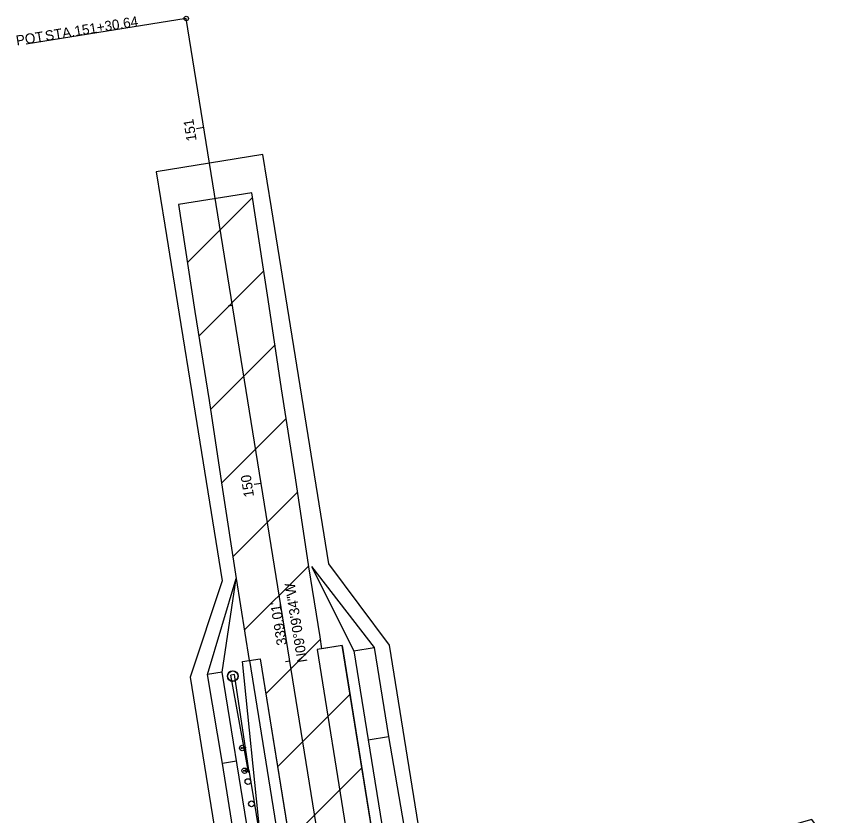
# Model space of a CAD drawing. Extents: x 195197 to 195502, y 336876 to 337459.
# Drawn here: x 195235.7 to 195462.3, y 337237.7 to 337459.5 of the extents above; entities that cross this region are included whole.
import ezdxf

# ---------------------------------------------------------------- set-up
doc = ezdxf.new("R2010")
doc.units = 0
for name, color, linetype in [('_CIVIL_CONSTRUCTION', 7, 'Continuous'), ('DR_P_Cells', 7, 'Continuous'), ('DR_P_Culvert', 7, 'Continuous'), ('DR_P_Headwall', 7, 'Continuous'), ('DT_X_Island', 7, 'Continuous'), ('DT_X_Terrain_Ground_Line', 7, 'Continuous'), ('DT_X_Void', 7, 'Continuous'), ('GK_Drainage_Nodes', 7, 'Continuous'), ('MD_P_Surface_Finished_Grade', 7, 'Continuous'), ('PV_P_Shoulder', 7, 'Continuous'), ('SC_Scratch1', 7, 'Continuous')]:
    doc.layers.add(name, color=color, linetype=linetype)

msp = doc.modelspace()

# ---------------------------------------------------------------- linework, layer by layer
at = {"layer": '_CIVIL_CONSTRUCTION'}
for points in [[(195306.55, 337406.32), (195304.16, 337421.13), (195274.54, 337416.35)], [(195274.54, 337416.35), (195276.93, 337401.54), (195280.91, 337376.86), (195284.89, 337352.18), (195288.87, 337327.5), (195292.85, 337302.82), (195283.99, 337276.07), (195287.97, 337251.38), (195291.95, 337226.7)], [(195415.16, 337192.63), (195427.5, 337191.06), (195439.23, 337196.72), (195449.47, 337204.35), (195456.27, 337211.36), (195462.31, 337228.75), (195456.54, 337236.65), (195437.52, 337231.22), (195415.54, 337222.22), (195377.07, 337205.9), (195368.38, 337218.99), (195350.22, 337217.12), (195339.28, 337284.98), (195322.46, 337307.59), (195306.55, 337406.32)]]:
    msp.add_lwpolyline(points, dxfattribs=at)
at = {"layer": 'DR_P_Cells'}
for p, q in [((195300.46, 337280.75), (195325.98, 337122.42)), ((195303.42, 337281.22), (195318.86, 337185.46))]:
    msp.add_line(p, q, dxfattribs=at)
at = {"layer": 'DR_P_Headwall'}
for p, q in [((195282.88, 337458.86), (195238.45, 337451.7)), ((195287.76, 337428.61), (195285.78, 337428.29)), ((195295.72, 337379.25), (195294.53, 337379.06)), ((195303.68, 337329.88), (195301.7, 337329.57)), ((195311.64, 337280.52), (195310.45, 337280.33))]:
    msp.add_line(p, q, dxfattribs=at)
msp.add_circle((195282.88, 337458.86), 0.6, dxfattribs=at)
at = {"layer": 'DT_X_Island'}
for p, q in [((195326.13, 337284.88), (195319.21, 337283.77)), ((195319.21, 337283.77), (195334.66, 337188.01)), ((195326.13, 337284.88), (195341.57, 337189.12))]:
    msp.add_line(p, q, dxfattribs=at)
at = {"layer": 'DT_X_Terrain_Ground_Line'}
msp.add_line((195300.3, 337250.33), (195300.38, 337249.84), dxfattribs=at)
at = {"layer": 'DT_X_Void'}
for p, q in [((195283.21, 337391.16), (195301.28, 337409.23)), ((195286.38, 337370.76), (195304.43, 337388.81)), ((195289.59, 337350.4), (195307.53, 337368.34)), ((195292.71, 337329.94), (195310.64, 337347.88)), ((195295.84, 337309.5), (195313.78, 337327.45)), ((195299.01, 337289.11), (195316.87, 337306.97)), ((195304.98, 337271.51), (195320.14, 337286.66)), ((195308.26, 337251.21), (195328.32, 337271.28)), ((195311.53, 337230.92), (195331.59, 337250.98))]:
    msp.add_line(p, q, dxfattribs=at)
msp.add_lwpolyline([(195336.13, 337222.85), (195326.13, 337284.88), (195320.55, 337283.99), (195320.04, 337287.31), (195316.91, 337306.7), (195313.18, 337331.42), (195309.37, 337356.13), (195305.66, 337380.85), (195301.85, 337405.56), (195301.09, 337410.5), (195280.75, 337407.22), (195285.3, 337377.57), (195289.21, 337352.88), (195292.98, 337328.16), (195296.76, 337303.45), (195300.33, 337280.72), (195303.42, 337281.22), (195318.86, 337185.46)], dxfattribs=at)
at = {"layer": 'GK_Drainage_Nodes'}
for p, q in [((195298.48, 337280.43), (195303.42, 337281.22)), ((195303.8, 337228.61), (195298.48, 337280.43))]:
    msp.add_line(p, q, dxfattribs=at)
at = {"layer": 'MD_P_Surface_Finished_Grade'}
for p, q in [((195294.39, 337276.24), (195294.31, 337276.23)), ((195294.31, 337276.23), (195294.31, 337276.23)), ((195296.25, 337276.8), (195295.24, 337276.65)), ((195300.03, 337250.3), (195295.24, 337276.65)), ((195295.64, 337277.88), (195295.64, 337277.88)), ((195295.65, 337277.8), (195295.64, 337277.88)), ((195300.3, 337250.33), (195296.25, 337276.8)), ((195297.21, 337276.55), (195297.29, 337276.56)), ((195297.29, 337276.56), (195297.29, 337276.56)), ((195295.96, 337274.98), (195295.97, 337274.9)), ((195295.97, 337274.9), (195295.97, 337274.9)), ((195297.68, 337256.37), (195297.68, 337256.37)), ((195298.16, 337256.58), (195298.16, 337256.58)), ((195298.16, 337256.58), (195298.18, 337256.58)), ((195298.19, 337256.25), (195298.16, 337256.58)), ((195298.19, 337256.25), (195298.16, 337256.58)), ((195298.16, 337256.58), (195298.18, 337256.58)), ((195298.18, 337256.58), (195298.18, 337256.58)), ((195298.18, 337256.58), (195298.19, 337256.45)), ((195298.18, 337256.58), (195298.19, 337256.45)), ((195298.18, 337256.33), (195298.2, 337256.34)), ((195298.19, 337256.29), (195298.18, 337256.33)), ((195298.18, 337256.31), (195298.2, 337256.31)), ((195298.18, 337256.31), (195298.2, 337256.31)), ((195298.19, 337256.45), (195298.19, 337256.45)), ((195298.19, 337256.29), (195298.2, 337256.29)), ((195298.19, 337256.25), (195298.19, 337256.25)), ((195298.21, 337256.25), (195298.19, 337256.25)), ((195298.21, 337256.25), (195298.19, 337256.25)), ((195298.2, 337256.38), (195298.2, 337256.38)), ((195298.2, 337256.38), (195298.21, 337256.25)), ((195298.2, 337256.38), (195298.21, 337256.25)), ((195298.2, 337256.29), (195298.2, 337256.34)), ((195298.21, 337256.25), (195298.21, 337256.25)), ((195298.22, 337256.42), (195298.62, 337256.46)), ((195298.22, 337256.42), (195298.62, 337256.46)), ((195298.63, 337256.45), (195298.22, 337256.41)), ((195298.63, 337256.45), (195298.22, 337256.41)), ((195298.22, 337256.42), (195298.22, 337256.42)), ((195298.22, 337256.41), (195298.22, 337256.41)), ((195298.36, 337257.18), (195298.36, 337257.18)), ((195298.49, 337255.69), (195298.49, 337255.69)), ((195298.62, 337256.46), (195298.62, 337256.46)), ((195298.63, 337256.45), (195298.63, 337256.45)), ((195298.64, 337256.62), (195298.64, 337256.62)), ((195298.64, 337256.62), (195298.66, 337256.62)), ((195298.65, 337256.49), (195298.64, 337256.62)), ((195298.65, 337256.49), (195298.64, 337256.62)), ((195298.64, 337256.62), (195298.66, 337256.62)), ((195298.65, 337256.49), (195298.65, 337256.49)), ((195298.66, 337256.62), (195298.69, 337256.29)), ((195298.66, 337256.62), (195298.69, 337256.29)), ((195298.66, 337256.62), (195298.67, 337256.62)), ((195298.66, 337256.62), (195298.66, 337256.62)), ((195298.67, 337256.62), (195298.66, 337256.62)), ((195298.66, 337256.62), (195298.66, 337256.62)), ((195298.66, 337256.62), (195298.69, 337256.29)), ((195298.66, 337256.62), (195298.69, 337256.29)), ((195298.66, 337256.42), (195298.66, 337256.42)), ((195298.67, 337256.29), (195298.66, 337256.42)), ((195298.67, 337256.29), (195298.66, 337256.42)), ((195298.67, 337256.33), (195298.66, 337256.38)), ((195298.66, 337256.38), (195298.68, 337256.38)), ((195298.66, 337256.35), (195298.68, 337256.36)), ((195298.66, 337256.35), (195298.68, 337256.36)), ((195298.67, 337256.62), (195298.69, 337256.5)), ((195298.67, 337256.62), (195298.69, 337256.5)), ((195298.67, 337256.62), (195298.67, 337256.62)), ((195298.67, 337256.33), (195298.68, 337256.33)), ((195298.67, 337256.29), (195298.67, 337256.29)), ((195298.69, 337256.29), (195298.67, 337256.29)), ((195298.69, 337256.29), (195298.67, 337256.29)), ((195298.68, 337256.33), (195298.68, 337256.38)), ((195298.69, 337256.5), (195298.69, 337256.5)), ((195298.69, 337256.42), (195298.69, 337256.42)), ((195298.69, 337256.42), (195298.71, 337256.3)), ((195298.69, 337256.42), (195298.71, 337256.3)), ((195298.69, 337256.29), (195298.71, 337256.3)), ((195298.71, 337256.3), (195298.69, 337256.29)), ((195298.69, 337256.29), (195298.69, 337256.29)), ((195298.69, 337256.29), (195298.69, 337256.29)), ((195298.71, 337256.3), (195298.71, 337256.3)), ((195299.32, 337256.53), (195298.72, 337256.47)), ((195299.32, 337256.51), (195298.72, 337256.46)), ((195298.72, 337256.47), (195298.87, 337256.48)), ((195298.72, 337256.47), (195298.72, 337256.47)), ((195298.72, 337256.46), (195298.87, 337256.47)), ((195298.72, 337256.46), (195298.72, 337256.46)), ((195298.87, 337256.48), (195299.32, 337256.53)), ((195298.87, 337256.47), (195299.32, 337256.51)), ((195299.34, 337256.68), (195298.89, 337256.64)), ((195298.89, 337256.64), (195298.9, 337256.52)), ((195298.89, 337256.64), (195298.91, 337256.64)), ((195298.9, 337256.52), (195299.35, 337256.56)), ((195298.91, 337256.64), (195299.35, 337256.69)), ((195298.91, 337256.64), (195298.94, 337256.32)), ((195298.91, 337256.44), (195299.36, 337256.48)), ((195298.91, 337256.44), (195298.92, 337256.32)), ((195299.37, 337256.36), (195298.92, 337256.32)), ((195298.92, 337256.32), (195298.94, 337256.32)), ((195298.94, 337256.32), (195299.38, 337256.36)), ((195299.17, 337256.5), (195299.17, 337256.5)), ((195299.35, 337256.69), (195299.34, 337256.68)), ((195299.34, 337256.68), (195299.37, 337256.36)), ((195299.35, 337256.69), (195299.38, 337256.36)), ((195299.36, 337256.48), (195299.35, 337256.56)), ((195299.38, 337256.36), (195299.37, 337256.36)), ((195298.36, 337250.02), (195298.36, 337250.02)), ((195298.83, 337250.26), (195298.83, 337250.26)), ((195298.83, 337250.26), (195298.84, 337250.26)), ((195298.88, 337249.94), (195298.83, 337250.26)), ((195298.88, 337249.94), (195298.83, 337250.26)), ((195298.83, 337250.26), (195298.84, 337250.26)), ((195298.84, 337250.26), (195298.84, 337250.26)), ((195298.84, 337250.26), (195298.86, 337250.14)), ((195298.84, 337250.26), (195298.86, 337250.14)), ((195298.86, 337250.14), (195298.86, 337250.14)), ((195298.87, 337249.97), (195298.86, 337250.02)), ((195298.86, 337250.02), (195298.88, 337250.02)), ((195298.87, 337250), (195298.89, 337250)), ((195298.87, 337250), (195298.89, 337250)), ((195298.87, 337249.97), (195298.89, 337249.98)), ((195298.88, 337250.06), (195298.88, 337250.06)), ((195298.88, 337250.06), (195298.9, 337249.94)), ((195298.88, 337250.06), (195298.9, 337249.94)), ((195298.89, 337249.98), (195298.88, 337250.02)), ((195298.88, 337249.94), (195298.88, 337249.94)), ((195298.9, 337249.94), (195298.88, 337249.94)), ((195298.9, 337249.94), (195298.88, 337249.94)), ((195298.9, 337250.11), (195299.3, 337250.18)), ((195298.9, 337250.11), (195299.3, 337250.18)), ((195299.3, 337250.16), (195298.9, 337250.1)), ((195299.3, 337250.16), (195298.9, 337250.1)), ((195298.9, 337250.11), (195298.9, 337250.11)), ((195298.9, 337250.1), (195298.9, 337250.1)), ((195298.9, 337249.94), (195298.9, 337249.94)), ((195298.98, 337250.88), (195298.98, 337250.88)), ((195299.22, 337249.4), (195299.22, 337249.4)), ((195299.3, 337250.34), (195299.3, 337250.34)), ((195299.3, 337250.34), (195299.32, 337250.34)), ((195299.32, 337250.21), (195299.3, 337250.34)), ((195299.32, 337250.21), (195299.3, 337250.34)), ((195299.3, 337250.34), (195299.32, 337250.34)), ((195299.3, 337250.18), (195299.3, 337250.18)), ((195299.3, 337250.16), (195299.3, 337250.16)), ((195299.97, 337250.51), (195299.31, 337250.4)), ((195299.97, 337250.51), (195299.31, 337250.4)), ((195299.31, 337250.4), (195299.31, 337250.4)), ((195299.31, 337250.4), (195299.38, 337249.95)), ((195299.31, 337250.4), (195299.38, 337249.95)), ((195299.32, 337250.34), (195299.32, 337250.34)), ((195299.32, 337250.34), (195299.37, 337250.02)), ((195299.32, 337250.34), (195299.37, 337250.02)), ((195299.32, 337250.21), (195299.32, 337250.21)), ((195299.33, 337250.14), (195299.33, 337250.14)), ((195299.35, 337250.01), (195299.33, 337250.14)), ((195299.35, 337250.01), (195299.33, 337250.14)), ((195299.35, 337250.05), (195299.34, 337250.1)), ((195299.34, 337250.1), (195299.36, 337250.1)), ((195299.34, 337250.07), (195299.36, 337250.08)), ((195299.34, 337250.07), (195299.36, 337250.08)), ((195299.35, 337250.05), (195299.37, 337250.05)), ((195299.37, 337250.02), (195299.35, 337250.01)), ((195299.37, 337250.02), (195299.35, 337250.01)), ((195299.35, 337250.01), (195299.35, 337250.01)), ((195299.36, 337250.1), (195300.02, 337250.21)), ((195299.36, 337250.08), (195300.02, 337250.18)), ((195299.36, 337250.08), (195300.02, 337250.18)), ((195299.37, 337250.05), (195299.36, 337250.1)), ((195299.37, 337250.05), (195299.36, 337250.1)), ((195299.37, 337250.05), (195300.02, 337250.16)), ((195299.37, 337250.02), (195299.37, 337250.02)), ((195299.38, 337249.95), (195300.04, 337250.06)), ((195299.38, 337249.95), (195300.04, 337250.06)), ((195299.38, 337249.95), (195299.38, 337249.95)), ((195299.84, 337250.26), (195299.84, 337250.26)), ((195299.97, 337250.51), (195299.97, 337250.51)), ((195300.04, 337250.06), (195299.97, 337250.51)), ((195300.04, 337250.06), (195299.97, 337250.51)), ((195300.02, 337250.16), (195300.02, 337250.21)), ((195300.03, 337250.29), (195300.3, 337250.33)), ((195300.04, 337250.06), (195300.04, 337250.06)), ((195300.12, 337249.8), (195300.38, 337249.84)), ((195300.3, 337250.33), (195302.29, 337237.99)), ((195302.29, 337237.99), (195304.28, 337225.65))]:
    msp.add_line(p, q, dxfattribs=at)
for centre, radius in [((195295.8, 337276.39), 1.5), ((195295.8, 337276.39), 1.5), ((195295.8, 337276.39), 1.42), ((195298.42, 337256.44), 0.75), ((195298.42, 337256.44), 0.75), ((195299.1, 337250.14), 0.75), ((195299.1, 337250.14), 0.75), ((195300, 337247.12), 0.8), ((195301, 337240.95), 0.8)]:
    msp.add_circle(centre, radius, dxfattribs=at)
for centre, start, end in [((195298.22, 337256.45), 185.28, 275.28), ((195298.22, 337256.45), 185.28, 275.28), ((195298.23, 337256.38), 95.28, 185.28), ((195298.23, 337256.38), 95.28, 185.28), ((195298.62, 337256.49), 275.28, 5.28), ((195298.62, 337256.49), 275.28, 5.28), ((195298.63, 337256.42), 5.28, 95.28), ((195298.63, 337256.42), 5.28, 95.28), ((195298.72, 337256.5), 185.28, 275.28), ((195298.72, 337256.5), 185.28, 275.28), ((195298.72, 337256.43), 95.28, 185.28), ((195298.72, 337256.43), 95.28, 185.28), ((195298.89, 337250.14), 189.1593, 279.1593), ((195298.89, 337250.14), 189.1593, 279.1593), ((195298.91, 337250.07), 99.1593, 189.1593), ((195298.91, 337250.07), 99.1593, 189.1593), ((195299.29, 337250.21), 279.1593, 9.1593), ((195299.29, 337250.21), 279.1593, 9.1593), ((195299.3, 337250.13), 9.1593, 99.1593), ((195299.3, 337250.13), 9.1593, 99.1593)]:
    msp.add_arc(centre, 0.03, start, end, dxfattribs=at)
for centre, major_axis, ratio, start_param, end_param in [((195298.87, 337256.51), (0.0324, 0.003), 0.923077, 4.712389, 6.283185), ((195298.88, 337256.44), (-0.0324, -0.003), 0.923077, 3.141593, 4.712389), ((195299.32, 337256.55), (0.0308, 0.0028), 0.969864, 4.712389, 6.283185), ((195299.32, 337256.48), (-0.0308, -0.0028), 0.969864, 3.141593, 4.712389)]:
    msp.add_ellipse(centre, major_axis=major_axis, ratio=ratio, start_param=start_param, end_param=end_param, dxfattribs=at)
msp.add_open_spline([(195300.12, 337249.8), (195300.1, 337249.92), (195300.07, 337250.05), (195300.05, 337250.19), (195300.05, 337250.22), (195300.04, 337250.23), (195300.04, 337250.26), (195300.04, 337250.28), (195300.03, 337250.29)], degree=3, dxfattribs=at)
at = {"layer": 'PV_P_Shoulder'}
for p, q in [((195317.68, 337306.82), (195335.09, 337284.3)), ((195317.68, 337306.82), (195329.41, 337283.39)), ((195288.81, 337276.84), (195296.76, 337303.45)), ((195292.88, 337277.5), (195296.76, 337303.45)), ((195329.41, 337283.39), (195335.09, 337284.3)), ((195329.41, 337283.39), (195333.39, 337258.71)), ((195335.09, 337284.3), (195338.99, 337259.61)), ((195292.88, 337277.5), (195288.81, 337276.84)), ((195292.91, 337252.18), (195288.81, 337276.84)), ((195300.84, 337228.14), (195292.88, 337277.5)), ((195333.39, 337258.71), (195338.99, 337259.61)), ((195333.39, 337258.71), (195339.74, 337219.26)), ((195338.99, 337259.61), (195343.29, 337234.98)), ((195296.86, 337252.82), (195292.91, 337252.18)), ((195296.89, 337227.5), (195292.91, 337252.18))]:
    msp.add_line(p, q, dxfattribs=at)
at = {"layer": 'SC_Scratch1'}
msp.add_line((195336.84, 337124.17), (195282.88, 337458.86), dxfattribs=at)

# ---------------------------------------------------------------- texts
at = {"layer": 'DR_P_Culvert'}
for s, p in [('N09°09\'34"W', (195316.52, 337280.4)), ("339.01'", (195310.85, 337285.15))]:
    msp.add_text(s, height=2.8, rotation=99.1593, dxfattribs=at).set_placement(p)
at = {"layer": 'DR_P_Headwall'}
for s, rotation, p in [('151+30.64', 9.1593, (195252.11, 337453.94)), ('POT', 9.1593, (195235.87, 337451.32)), (' STA. ', 9.1593, (195242.91, 337452.45)), ('151', 99.1593, (195285.8, 337425.03)), ('150', 99.1593, (195301.73, 337326.26))]:
    msp.add_text(s, height=2.8, rotation=rotation, dxfattribs=at).set_placement(p)

doc.saveas('drawing.dxf')
